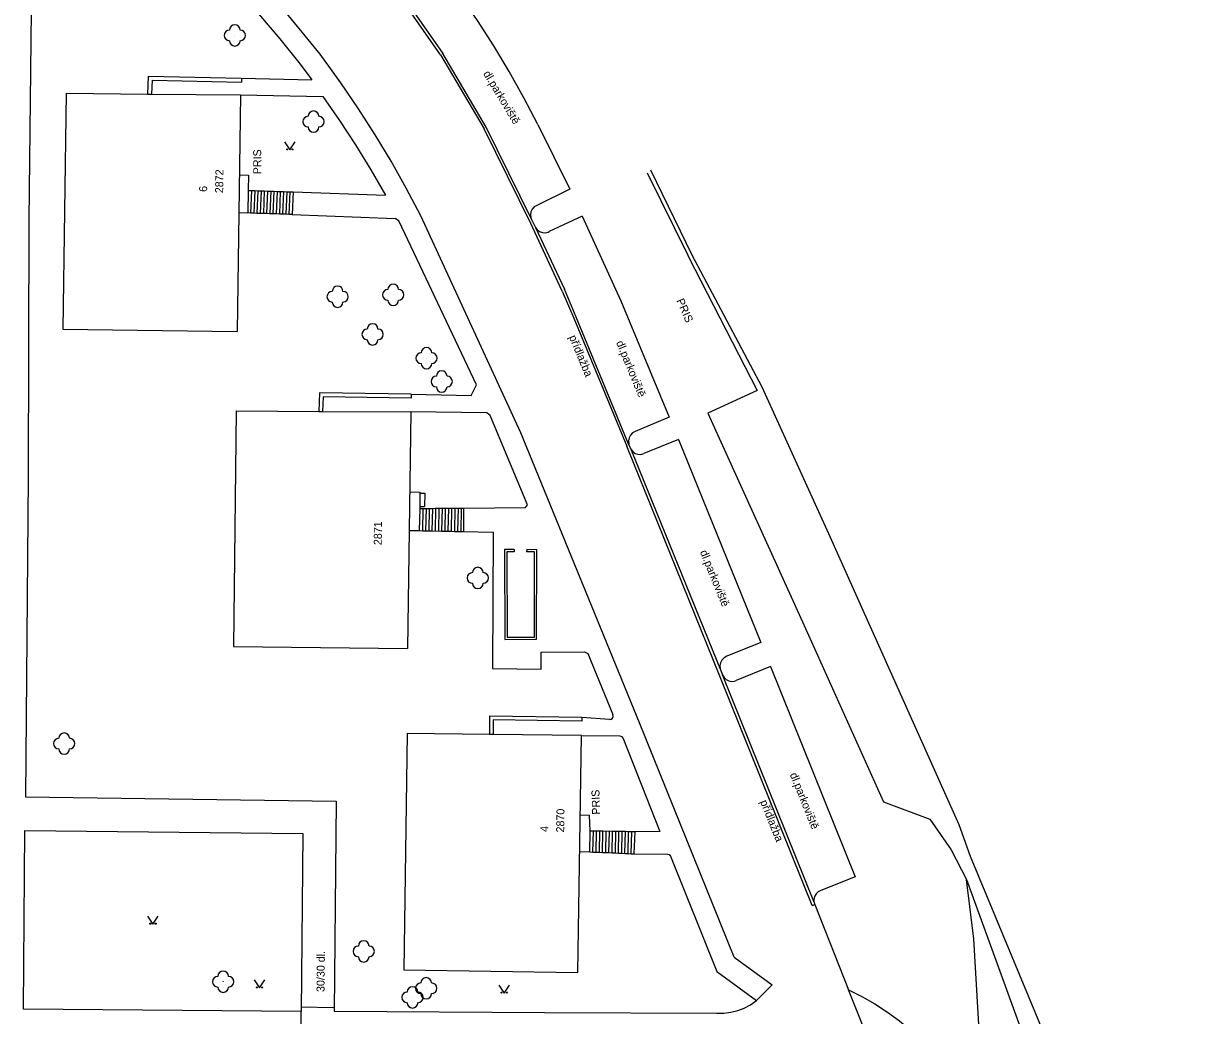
# Model space of a CAD drawing. Extents: x -584400 to -581602, y -1210894 to -1208793.
# Drawn here: x -583057.7 to -582947.9, y -1210410.6 to -1210317.6 of the extents above; entities that cross this region are included whole.
import ezdxf

# ---------------------------------------------------------------- set-up
doc = ezdxf.new("R2010")
doc.units = 0
for name, color, linetype in [('BUDOVY_MĚŘ', 7, 'Continuous'), ('POMOC_POPIS', 7, 'Continuous'), ('ROZHRANÍ_PLOCH', 7, 'Continuous'), ('VÝŠKOPIS', 7, 'Continuous'), ('ZELEŇ', 7, 'Continuous'), ('ZN_DOPLŇKOVÉ', 7, 'Continuous'), ('ZN_KULTUR', 7, 'Continuous'), ('Č_POPIS_EVID', 7, 'Continuous')]:
    doc.layers.add(name, color=color, linetype=linetype)

msp = doc.modelspace()

# ---------------------------------------------------------------- linework, layer by layer
at = {"layer": 'BUDOVY_MĚŘ'}
for points in [[(-583053.67, -1210324.14), (-583053.97, -1210346.24), (-583037.63, -1210346.47)], [(-583053.67, -1210324.14), (-583046.02, -1210324.21), (-583045.64, -1210324.21), (-583037.34, -1210324.28), (-583037.63, -1210346.47)], [(-583037.73, -1210353.92), (-583038, -1210376.01), (-583021.69, -1210376.2)], [(-583037.73, -1210353.92), (-583030, -1210353.96), (-583029.64, -1210353.96), (-583021.38, -1210354.01), (-583021.69, -1210376.2)], [(-583005.73, -1210406.55), (-583005.37, -1210384.34), (-583013.67, -1210384.24), (-583014.01, -1210384.24), (-583021.72, -1210384.16), (-583022.04, -1210406.3), (-583005.73, -1210406.55)]]:
    msp.add_lwpolyline(points, dxfattribs=at)
at = {"layer": 'ROZHRANÍ_PLOCH'}
for points in [[(-583056.88, -1210300.54), (-583056.8, -1210300.24), (-583056.64, -1210299.97), (-583056.42, -1210299.74), (-583056.16, -1210299.58), (-583055.86, -1210299.5), (-583055.55, -1210299.49), (-583055.21, -1210299.57), (-583053.05, -1210300.9), (-583044.17, -1210306.49), (-583035.77, -1210312.66), (-583035.63, -1210316.68), (-583033.66, -1210319.02), (-583031.75, -1210321.41), (-583030.65, -1210322.87)], [(-583018.59, -1210320.54), (-583021.78, -1210315.97), (-583027.62, -1210308.1), (-583031.57, -1210304.04), (-583033.34, -1210302.49)], [(-583056.92, -1210313.58), (-583057.15, -1210336), (-583057.24, -1210360.16), (-583057.48, -1210390.1), (-583028.36, -1210390.49), (-583028.57, -1210410.19), (-583008.84, -1210410.32), (-582992.7, -1210410.37), (-582992.04, -1210410.37), (-582991.38, -1210410.29), (-582990.74, -1210410.13), (-582990.13, -1210409.89), (-582989.54, -1210409.58), (-582988.99, -1210409.2)], [(-583009.46, -1210327.05), (-583010.77, -1210324.56), (-583012.15, -1210322.1), (-583013.6, -1210319.68), (-583015.12, -1210317.3), (-583016.71, -1210314.96), (-583016.85, -1210314.77)], [(-582991.08, -1210405.12), (-582999.95, -1210383.16), (-583011.08, -1210355.98), (-583020.45, -1210335.61), (-583021.81, -1210333.04), (-583023.23, -1210330.51), (-583024.72, -1210328.02), (-583026.29, -1210325.58), (-583027.92, -1210323.17), (-583029.87, -1210320.47), (-583033.67, -1210315.8)], [(-583021.7, -1210315.72), (-583021.07, -1210316.57), (-583018.38, -1210320.42)], [(-583018.59, -1210320.54), (-583014.51, -1210327.47)], [(-583010.08, -1210335.95), (-583014.3, -1210327.31), (-583018.38, -1210320.42)], [(-583037.23, -1210322.72), (-583030.65, -1210322.87)], [(-583037.34, -1210324.28), (-583029.61, -1210324.43), (-583028.04, -1210326.68), (-583026.55, -1210328.97), (-583025.12, -1210331.31), (-583023.75, -1210333.69)], [(-583009.46, -1210327.05), (-583006.47, -1210333.12), (-583009.58, -1210334.65)], [(-583007.2, -1210342.68), (-583010.13, -1210336.35), (-583014.51, -1210327.47)], [(-583037.44, -1210331.79), (-583036.57, -1210331.82), (-583036.6, -1210333.25)], [(-583036.6, -1210333.25), (-583036.65, -1210335.35)], [(-583036.6, -1210333.25), (-583036.3, -1210333.26)], [(-583036.3, -1210333.26), (-583036.39, -1210335.36)], [(-583036.3, -1210333.26), (-583036, -1210333.26)], [(-583036, -1210333.26), (-583036.09, -1210335.38)], [(-583036, -1210333.26), (-583035.7, -1210333.27)], [(-583035.7, -1210333.27), (-583035.79, -1210335.39)], [(-583035.7, -1210333.27), (-583035.4, -1210333.28)], [(-583035.4, -1210333.28), (-583035.49, -1210335.4)], [(-583035.4, -1210333.28), (-583035.1, -1210333.29)], [(-583035.1, -1210333.29), (-583035.19, -1210335.41)], [(-583035.1, -1210333.29), (-583034.8, -1210333.3)], [(-583034.8, -1210333.3), (-583034.89, -1210335.42)], [(-583034.8, -1210333.3), (-583034.5, -1210333.31)], [(-583034.5, -1210333.31), (-583034.59, -1210335.43)], [(-583034.5, -1210333.31), (-583034.2, -1210333.32)], [(-583034.2, -1210333.32), (-583034.29, -1210335.44)], [(-583034.2, -1210333.32), (-583033.9, -1210333.33)], [(-583033.9, -1210333.33), (-583033.99, -1210335.45)], [(-583033.9, -1210333.33), (-583033.6, -1210333.34)], [(-583033.6, -1210333.34), (-583033.69, -1210335.46)], [(-583033.6, -1210333.34), (-583033.3, -1210333.35)], [(-583033.3, -1210333.35), (-583033.39, -1210335.47)], [(-583033.3, -1210333.35), (-583033, -1210333.36)], [(-583033, -1210333.36), (-583033.09, -1210335.48)], [(-583033, -1210333.36), (-583032.7, -1210333.37)], [(-583032.7, -1210333.37), (-583032.79, -1210335.49)], [(-583032.7, -1210333.37), (-583032.4, -1210333.38)], [(-583032.4, -1210333.38), (-583032.49, -1210335.5)], [(-583032.4, -1210333.38), (-583023.75, -1210333.69)], [(-583009.58, -1210334.65), (-583009.82, -1210334.79), (-583010, -1210335), (-583010.12, -1210335.26), (-583010.17, -1210335.53), (-583010.13, -1210335.81), (-583010.07, -1210335.98), (-583009.7, -1210336.72), (-583006.98, -1210342.5)], [(-583037.48, -1210335.32), (-583036.65, -1210335.35)], [(-583036.39, -1210335.36), (-583036.65, -1210335.35)], [(-583036.09, -1210335.38), (-583036.39, -1210335.36)], [(-583035.79, -1210335.39), (-583036.09, -1210335.38)], [(-583035.49, -1210335.4), (-583035.79, -1210335.39)], [(-583035.19, -1210335.41), (-583035.49, -1210335.4)], [(-583034.89, -1210335.42), (-583035.19, -1210335.41)], [(-583034.59, -1210335.43), (-583034.89, -1210335.42)], [(-583034.29, -1210335.44), (-583034.59, -1210335.43)], [(-583033.99, -1210335.45), (-583034.29, -1210335.44)], [(-583033.69, -1210335.46), (-583033.99, -1210335.45)], [(-583033.39, -1210335.47), (-583033.69, -1210335.46)], [(-583033.09, -1210335.48), (-583033.39, -1210335.47)], [(-583032.79, -1210335.49), (-583033.09, -1210335.48)], [(-583032.49, -1210335.5), (-583032.79, -1210335.49)], [(-583032.49, -1210335.5), (-583022.85, -1210335.86)], [(-583021.34, -1210352.35), (-583015.72, -1210352.48), (-583015.22, -1210351.46), (-583022.5, -1210336.09), (-583022.85, -1210335.86)], [(-583005.32, -1210335.64), (-583008.42, -1210337.1)], [(-583005.32, -1210335.64), (-583001.7, -1210343.58), (-582997.16, -1210354.5), (-583000.35, -1210355.83), (-583000.59, -1210355.98), (-583000.79, -1210356.18), (-583000.92, -1210356.43), (-583000.98, -1210356.71), (-583000.96, -1210356.99), (-583000.94, -1210357.09)], [(-583009.7, -1210336.72), (-583009.53, -1210336.94), (-583009.31, -1210337.1), (-583009.05, -1210337.19), (-583008.77, -1210337.21), (-583008.5, -1210337.14), (-583008.42, -1210337.1)], [(-583007.2, -1210342.68), (-583006.11, -1210345.21), (-583001.12, -1210357.22)], [(-583000.94, -1210357.09), (-583005.88, -1210345.12), (-583006.98, -1210342.5)], [(-582988.91, -1210352.01), (-582993.56, -1210354.12), (-582984.68, -1210373.68), (-582977.1, -1210390.56), (-582972.76, -1210392.19), (-582970.75, -1210395.07), (-582969.32, -1210397.85)], [(-583016.45, -1210363.03), (-583010.63, -1210362.98), (-583010.45, -1210362.73), (-583013.95, -1210354.33), (-583014.26, -1210354.09), (-583021.38, -1210354.01)], [(-582996.3, -1210356.6), (-582999.54, -1210357.92)], [(-582996.3, -1210356.6), (-582988.57, -1210375.61), (-582991.78, -1210376.92), (-582992.02, -1210377.06), (-582992.22, -1210377.27), (-582992.35, -1210377.52), (-582992.41, -1210377.79), (-582992.39, -1210378.08), (-582992.35, -1210378.2)], [(-582983.77, -1210400.27), (-582992.41, -1210378.78), (-583001.12, -1210357.22)], [(-583000.94, -1210357.09), (-583000.75, -1210357.51), (-582992.35, -1210378.2), (-582992.16, -1210378.65)], [(-583000.75, -1210357.51), (-583000.58, -1210357.73), (-583000.35, -1210357.89), (-583000.09, -1210357.98), (-582999.81, -1210357.99), (-582999.54, -1210357.92)], [(-583021.48, -1210361.51), (-583020.52, -1210361.52), (-583020.52, -1210361.62)], [(-583020.52, -1210361.62), (-583020.54, -1210362.87)], [(-583020.52, -1210361.62), (-583020.05, -1210361.63), (-583020.1, -1210362.87)], [(-583020.54, -1210363.05), (-583020.59, -1210365.13)], [(-583020.54, -1210362.87), (-583020.54, -1210363.05)], [(-583020.54, -1210362.87), (-583020.1, -1210362.87)], [(-583020.54, -1210363.05), (-583020.25, -1210363.05)], [(-583020.25, -1210363.05), (-583020.29, -1210365.14)], [(-583020.25, -1210363.05), (-583019.95, -1210363.05)], [(-583019.95, -1210363.05), (-583019.99, -1210365.15)], [(-583019.95, -1210363.05), (-583019.65, -1210363.05)], [(-583019.65, -1210363.05), (-583019.69, -1210365.16)], [(-583019.65, -1210363.05), (-583019.35, -1210363.05)], [(-583019.35, -1210363.05), (-583019.39, -1210365.17)], [(-583019.35, -1210363.05), (-583019.05, -1210363.04)], [(-583019.05, -1210363.04), (-583019.09, -1210365.16)], [(-583019.05, -1210363.04), (-583018.75, -1210363.04)], [(-583018.75, -1210363.04), (-583018.79, -1210365.17)], [(-583018.75, -1210363.04), (-583018.45, -1210363.04)], [(-583018.45, -1210363.04), (-583018.49, -1210365.19)], [(-583018.45, -1210363.04), (-583018.15, -1210363.04)], [(-583018.15, -1210363.04), (-583018.19, -1210365.18)], [(-583018.15, -1210363.04), (-583017.85, -1210363.04)], [(-583017.85, -1210363.04), (-583017.89, -1210365.2)], [(-583017.85, -1210363.04), (-583017.55, -1210363.04)], [(-583017.55, -1210363.04), (-583017.59, -1210365.2)], [(-583017.55, -1210363.04), (-583017.25, -1210363.04)], [(-583017.25, -1210363.04), (-583017.29, -1210365.21)], [(-583017.25, -1210363.04), (-583016.95, -1210363.04)], [(-583016.95, -1210363.04), (-583016.99, -1210365.21)], [(-583016.95, -1210363.04), (-583016.65, -1210363.03)], [(-583016.65, -1210363.03), (-583016.69, -1210365.22)], [(-583016.65, -1210363.03), (-583016.45, -1210363.03)], [(-583016.45, -1210363.03), (-583016.43, -1210365.22)], [(-583021.53, -1210365.12), (-583020.59, -1210365.13)], [(-583020.59, -1210365.13), (-583020.29, -1210365.14)], [(-583020.29, -1210365.14), (-583019.99, -1210365.15)], [(-583019.99, -1210365.15), (-583019.69, -1210365.16)], [(-583019.69, -1210365.16), (-583019.39, -1210365.17)], [(-583019.39, -1210365.17), (-583018.49, -1210365.19)], [(-583018.49, -1210365.19), (-583017.89, -1210365.2)], [(-583017.89, -1210365.2), (-583017.59, -1210365.2)], [(-583017.59, -1210365.2), (-583017.29, -1210365.21)], [(-583017.29, -1210365.21), (-583016.99, -1210365.21)], [(-583016.99, -1210365.21), (-583016.69, -1210365.22)], [(-583016.69, -1210365.22), (-583016.43, -1210365.22)], [(-583016.43, -1210365.22), (-583013.65, -1210365.27), (-583013.71, -1210378.07), (-583009.17, -1210378.11), (-583009.15, -1210376.53), (-583005.1, -1210376.49), (-583004.78, -1210376.67), (-583002.44, -1210382.36)], [(-582983.6, -1210399.9), (-582992.16, -1210378.65)], [(-582992.16, -1210378.65), (-582992.03, -1210378.89), (-582991.84, -1210379.09), (-582991.59, -1210379.22), (-582991.32, -1210379.27), (-582991.05, -1210379.24), (-582990.89, -1210379.19)], [(-582987.68, -1210377.88), (-582990.89, -1210379.19)], [(-582987.68, -1210377.88), (-582979.75, -1210397.6), (-582982.96, -1210398.88)], [(-583002.76, -1210382.83), (-583005.34, -1210382.66)], [(-583002.76, -1210382.83), (-583002.6, -1210382.81), (-583002.48, -1210382.71), (-583002.41, -1210382.57), (-583002.44, -1210382.36)], [(-583005.37, -1210384.34), (-583001.79, -1210384.38), (-583001.63, -1210384.44), (-583001.49, -1210384.61), (-582998.04, -1210393.33), (-583000.34, -1210393.37)], [(-583005.49, -1210391.78), (-583004.62, -1210391.81)], [(-583004.57, -1210393.32), (-583004.62, -1210391.81)], [(-583031.64, -1210410.22), (-583057.67, -1210410), (-583057.54, -1210393.24), (-583031.49, -1210393.53), (-583031.64, -1210410.22)], [(-583004.61, -1210395.26), (-583004.57, -1210393.32)], [(-583004.27, -1210393.32), (-583004.57, -1210393.32)], [(-583004.31, -1210395.27), (-583004.27, -1210393.32)], [(-583003.97, -1210393.32), (-583004.27, -1210393.32)], [(-583004.01, -1210395.28), (-583003.97, -1210393.32)], [(-583003.67, -1210393.32), (-583003.97, -1210393.32)], [(-583003.71, -1210395.29), (-583003.67, -1210393.32)], [(-583003.37, -1210393.32), (-583003.67, -1210393.32)], [(-583003.41, -1210395.3), (-583003.37, -1210393.32)], [(-583002.47, -1210393.33), (-583003.37, -1210393.32)], [(-583003.11, -1210395.31), (-583003.07, -1210393.34)], [(-583002.81, -1210395.32), (-583002.77, -1210393.34)], [(-583002.51, -1210395.33), (-583002.47, -1210393.33)], [(-583001.87, -1210393.34), (-583002.47, -1210393.33)], [(-583002.21, -1210395.34), (-583002.17, -1210393.35)], [(-583001.91, -1210395.36), (-583001.87, -1210393.34)], [(-583001.57, -1210393.35), (-583001.87, -1210393.34)], [(-583001.61, -1210395.37), (-583001.57, -1210393.35)], [(-583001.27, -1210393.35), (-583001.57, -1210393.35)], [(-583001.31, -1210395.39), (-583001.27, -1210393.35)], [(-583000.97, -1210393.36), (-583001.27, -1210393.35)], [(-583001.02, -1210395.4), (-583000.97, -1210393.36)], [(-583000.67, -1210393.36), (-583000.97, -1210393.36)], [(-583000.72, -1210395.42), (-583000.67, -1210393.36)], [(-583000.34, -1210393.37), (-583000.67, -1210393.36)], [(-583000.44, -1210395.43), (-583000.34, -1210393.37)], [(-583005.54, -1210395.22), (-583004.61, -1210395.26)], [(-583004.61, -1210395.26), (-583004.31, -1210395.27)], [(-583004.31, -1210395.27), (-583004.01, -1210395.28)], [(-583004.01, -1210395.28), (-583003.71, -1210395.29)], [(-583003.71, -1210395.29), (-583003.41, -1210395.3)], [(-583003.41, -1210395.3), (-583003.11, -1210395.31)], [(-583003.11, -1210395.31), (-583002.81, -1210395.32)], [(-583002.81, -1210395.32), (-583002.51, -1210395.33)], [(-583002.51, -1210395.33), (-583002.21, -1210395.34)], [(-583002.21, -1210395.34), (-583001.91, -1210395.36)], [(-583001.91, -1210395.36), (-583001.61, -1210395.37)], [(-583001.61, -1210395.37), (-583001.31, -1210395.39)], [(-583001.31, -1210395.39), (-583001.02, -1210395.4)], [(-583001.02, -1210395.4), (-583000.72, -1210395.42)], [(-583000.72, -1210395.42), (-583000.44, -1210395.43)], [(-583000.44, -1210395.43), (-582997.31, -1210395.48), (-582997.17, -1210395.5), (-582997.03, -1210395.66), (-582992.71, -1210406.48), (-582988.99, -1210409.2)], [(-582966.02, -1210426.77), (-582966.57, -1210424.53), (-582967.05, -1210422.27), (-582967.45, -1210420), (-582967.82, -1210417.33), (-582968.62, -1210403.41), (-582969.32, -1210397.85)], [(-582969.32, -1210397.85), (-582963.95, -1210412.63)], [(-582982.96, -1210398.88), (-582983.21, -1210399.01), (-582983.41, -1210399.2), (-582983.55, -1210399.44), (-582983.61, -1210399.71), (-582983.6, -1210399.9)], [(-582983.77, -1210400.27), (-582983.52, -1210400.18)], [(-582983.6, -1210399.9), (-582983.52, -1210400.18)], [(-582983.52, -1210400.18), (-582980.37, -1210408.19)], [(-582991.08, -1210405.12), (-582987.52, -1210407.72)], [(-582988.99, -1210409.2), (-582987.52, -1210407.72)], [(-582977.11, -1210416.31), (-582980.37, -1210408.19)], [(-582980.37, -1210408.19), (-582979.11, -1210408.81), (-582977.9, -1210409.51), (-582976.72, -1210410.27), (-582975.59, -1210411.1), (-582974.51, -1210411.99), (-582973.48, -1210412.94), (-582972.51, -1210413.95), (-582971.59, -1210415.01), (-582970.74, -1210416.13), (-582969.95, -1210417.29), (-582969.52, -1210418), (-582966.02, -1210426.77)], [(-583031.66, -1210413.86), (-583031.64, -1210410.22)], [(-583031.64, -1210409.79), (-583028.62, -1210409.85)]]:
    msp.add_lwpolyline(points, dxfattribs=at)
at = {"layer": 'VÝŠKOPIS'}
msp.add_lwpolyline([(-582947.94, -1210446.89), (-582961.96, -1210412.47), (-582968.92, -1210395.69), (-582969.99, -1210392.71), (-582982.21, -1210365.45), (-582988.44, -1210351.68), (-582995.01, -1210339.3), (-582998.87, -1210331.34)], dxfattribs=at)
at = {"layer": 'ZELEŇ'}
for centre in [(-583037.86, -1210318.71), (-583030.49, -1210326.79), (-583028.23, -1210343.21), (-583023.02, -1210343.03), (-583024.95, -1210346.74), (-583019.9, -1210348.97), (-583018.48, -1210351.16), (-583015.1, -1210369.57), (-583053.85, -1210385.1), (-583025.79, -1210404.58), (-583038.96, -1210407.42), (-583019.93, -1210408.04), (-583021.22, -1210408.89)]:
    msp.add_circle(centre, 0.0005, dxfattribs=at)
for centre, start, end in [((-583038.36, -1210318.71), 90, 270), ((-583037.86, -1210318.21), 0, 180), ((-583037.36, -1210318.71), 270, 90), ((-583037.86, -1210319.21), 180, 360), ((-583030.49, -1210326.29), 0, 180), ((-583030.99, -1210326.79), 90, 270), ((-583030.49, -1210327.29), 180, 360), ((-583029.99, -1210326.79), 270, 90), ((-583028.73, -1210343.21), 90, 270), ((-583028.23, -1210342.71), 0, 180), ((-583027.73, -1210343.21), 270, 90), ((-583023.52, -1210343.03), 90, 270), ((-583023.02, -1210342.53), 0, 180), ((-583022.52, -1210343.03), 270, 90), ((-583028.23, -1210343.71), 180, 360), ((-583023.02, -1210343.53), 180, 360), ((-583024.95, -1210346.24), 0, 180), ((-583025.45, -1210346.74), 90, 270), ((-583024.45, -1210346.74), 270, 90), ((-583024.95, -1210347.24), 180, 360), ((-583019.9, -1210348.47), 0, 180), ((-583020.4, -1210348.97), 90, 270), ((-583019.4, -1210348.97), 270, 90), ((-583019.9, -1210349.47), 180, 360), ((-583018.48, -1210350.66), 0, 180), ((-583018.98, -1210351.16), 90, 270), ((-583017.98, -1210351.16), 270, 90), ((-583018.48, -1210351.66), 180, 360), ((-583015.6, -1210369.57), 90, 270), ((-583015.1, -1210369.07), 0, 180), ((-583014.6, -1210369.57), 270, 90), ((-583015.1, -1210370.07), 180, 360), ((-583053.85, -1210384.6), 0, 180), ((-583054.35, -1210385.1), 90, 270), ((-583053.35, -1210385.1), 270, 90), ((-583053.85, -1210385.6), 180, 360), ((-583026.29, -1210404.58), 90, 270), ((-583025.79, -1210404.08), 0, 180), ((-583025.29, -1210404.58), 270, 90), ((-583025.79, -1210405.08), 180, 360), ((-583039.46, -1210407.42), 90, 270), ((-583038.96, -1210406.92), 0, 180), ((-583038.46, -1210407.42), 270, 90), ((-583019.93, -1210407.54), 0, 180), ((-583038.96, -1210407.92), 180, 360), ((-583021.72, -1210408.89), 90, 270), ((-583021.22, -1210408.39), 0, 180), ((-583020.43, -1210408.04), 90, 270), ((-583020.72, -1210408.89), 270, 90), ((-583019.93, -1210408.54), 180, 360), ((-583019.43, -1210408.04), 270, 90), ((-583021.22, -1210409.39), 180, 360)]:
    msp.add_arc(centre, 0.5, start, end, dxfattribs=at)
at = {"layer": 'ZN_DOPLŇKOVÉ'}
for points in [[(-583046.02, -1210324.21), (-583045.94, -1210322.52), (-583037.23, -1210322.72), (-583037.23, -1210323.09)], [(-583045.64, -1210324.21), (-583045.59, -1210322.9), (-583037.23, -1210323.09)], [(-582999.23, -1210331.58), (-582995.43, -1210339.31)], [(-582995.43, -1210339.31), (-582995.36, -1210339.48)], [(-582995.36, -1210339.48), (-582988.91, -1210352.01)], [(-583021.34, -1210352.35), (-583029.94, -1210352.22), (-583030, -1210353.96)], [(-583021.34, -1210352.35), (-583021.34, -1210352.71), (-583029.6, -1210352.59), (-583029.64, -1210353.96)], [(-583011.68, -1210366.91), (-583012.6, -1210366.9), (-583012.56, -1210375.34), (-583009.59, -1210375.31), (-583009.57, -1210366.94), (-583010.51, -1210366.91), (-583010.52, -1210367.11)], [(-583011.68, -1210367.11), (-583012.39, -1210367.11), (-583012.36, -1210375.13), (-583009.79, -1210375.11), (-583009.77, -1210367.13), (-583010.52, -1210367.11)], [(-583011.68, -1210366.91), (-583011.68, -1210367.11)], [(-583005.34, -1210382.66), (-583014.01, -1210382.53), (-583014.01, -1210384.24)], [(-583005.34, -1210382.66), (-583005.34, -1210383), (-583013.67, -1210382.88), (-583013.67, -1210384.24)]]:
    msp.add_lwpolyline(points, dxfattribs=at)
at = {"layer": 'ZN_KULTUR'}
for points in [[(-583033.2, -1210328.7), (-583032.7, -1210329.45), (-583032.2, -1210328.7)], [(-583046.03, -1210401.28), (-583045.53, -1210402.03), (-583045.03, -1210401.28)], [(-583036.05, -1210407.26), (-583035.55, -1210408.01), (-583035.05, -1210407.26)], [(-583013.12, -1210407.74), (-583012.62, -1210408.49), (-583012.12, -1210407.74)]]:
    msp.add_lwpolyline(points, dxfattribs=at)
for centre in [(-583032.95, -1210329.4), (-583032.45, -1210329.4), (-583045.78, -1210401.98), (-583045.28, -1210401.98), (-583035.8, -1210407.96), (-583035.3, -1210407.96), (-583012.87, -1210408.44), (-583012.37, -1210408.44)]:
    msp.add_circle(centre, 0.05, dxfattribs=at)

# ---------------------------------------------------------------- texts
at = {"layer": 'POMOC_POPIS'}
for s, rotation, p in [('dl.parkoviště', 300.9953, (-583014.62, -1210322.29)), ('PRIS', 90, (-583035.39, -1210331.73)), ('PRIS', 293.6732, (-582996.51, -1210343.57)), ('přídlažba', 292.5657, (-583006.57, -1210346.98)), ('dl.parkoviště', 292.5558, (-583002.16, -1210347.5)), ('dl.parkoviště', 292.1125, (-582994.3, -1210367.13)), ('dl.parkoviště', 291.898, (-582985.88, -1210387.99)), ('PRIS', 91.8355, (-583003.63, -1210391.75)), ('přídlažba', 291.898, (-582988.66, -1210390.55)), ('30/30 dl.', 89.4823, (-583029.46, -1210408.39))]:
    msp.add_text(s, height=0.75, rotation=rotation, dxfattribs=at).set_placement(p)
at = {"layer": 'Č_POPIS_EVID'}
for s, rotation, p in [('2872', 89.2462, (-583038.96, -1210333.51)), ('6', 89.2462, (-583040.46, -1210333.38)), ('2871', 89.1996, (-583024.1, -1210366.5)), ('2870', 89.0741, (-583007.01, -1210393.44)), ('4', 89.0741, (-583008.51, -1210393.38))]:
    msp.add_text(s, height=0.75, rotation=rotation, dxfattribs=at).set_placement(p)

doc.saveas('drawing.dxf')
